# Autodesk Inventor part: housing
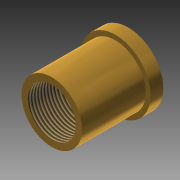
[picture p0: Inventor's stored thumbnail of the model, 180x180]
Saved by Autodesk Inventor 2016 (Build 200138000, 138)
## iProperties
Created: 2014-12
Part Number: housing
Material: Generic
Document SubType Name: Modeling
Designer: James
Density: 1 g/cm^3
Appearance: Brass - Satin
Author: James
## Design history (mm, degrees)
sketch "Sketch1"
  geometry: C1 r 4.75 at (0, 0); 1 further point
  constraints: 1 centre point, 1 coincident
  dimensions: "d0" = 9.5 diameter of C1
extrude "Extrusion1" new body sketch "Sketch1" distance "d1" = 10; taper "d2" = 0 deg
sketch "Sketch2"
  geometry: C1 r 4.75 at (0, 0) reference; C2 r 5.5 at (0, 0)
  constraints: 1 centre point, 1 coincident
  dimensions: "d3" = 11 diameter of C2
extrude "Extrusion2" join sketch "Sketch2" distance "d4" = 2; taper "d5" = 0 deg
sketch "Sketch3"
  geometry: C1 r 5.5 at (0, 0) reference; 1 further point
  constraints: 1 coincident
hole "Hole1" sketch "Sketch3" at (0, 0) diameter "d6" = 7.459; stored, may be unused: countersink angle "d10" = 90 deg, drill point angle "d12" = 118 deg; dims "d7" = 6, "d8" = 4, "d9" = 2, "d11" = 8
body "Solid1"
